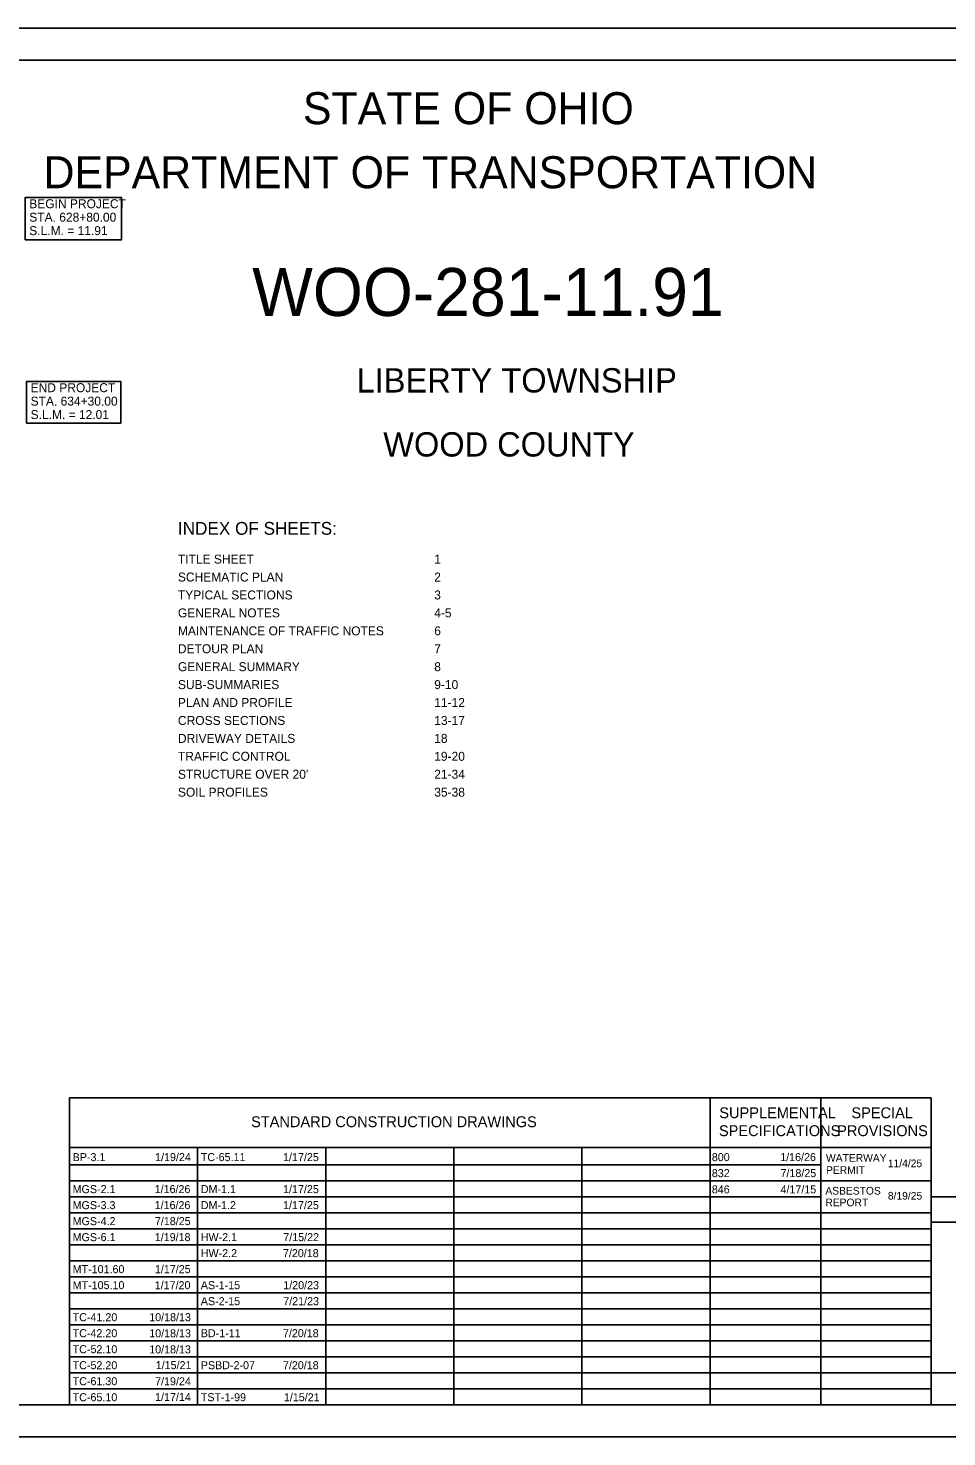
# Model space of a CAD drawing. Extents: x 0 to 39.4, y 0 to 22.
# Drawn here: x 9.51 to 23.84, y 0 to 22 of the extents above; entities that cross this region are included whole.
import ezdxf

# ---------------------------------------------------------------- set-up
doc = ezdxf.new("R2010")
doc.units = 0
for name, color, linetype in [('Default', 7, 'Continuous'), ('SH_Border', 7, 'Continuous'), ('SH_Cut_Line', 7, 'Continuous'), ('SH_Data', 7, 'Continuous'), ('SH_Text', 7, 'Continuous')]:
    doc.layers.add(name, color=color, linetype=linetype)

msp = doc.modelspace()

# ---------------------------------------------------------------- linework, layer by layer
at = {"layer": 'SH_Border'}
msp.add_lwpolyline([(1.5, 21.5), (33.5, 21.5), (33.5, 0.5), (1.5, 0.5)], close=True, dxfattribs=at)
at = {"layer": 'SH_Cut_Line'}
msp.add_lwpolyline([(0, 0), (34, 0), (34, 22), (0, 22)], close=True, dxfattribs=at)
at = {"layer": 'SH_Data'}
for p, q in [((10.15, 5.292), (23.6, 5.292)), ((10.15, 0.5), (10.15, 5.292)), ((20.15, 0.5), (20.15, 5.292)), ((21.875, 0.5), (21.875, 5.292)), ((23.6, 0.5), (23.6, 5.292)), ((10.15, 4.521), (23.6, 4.521)), ((12.15, 0.5), (12.15, 4.521)), ((14.15, 0.5), (14.15, 4.521)), ((16.15, 0.5), (16.15, 4.521)), ((18.15, 0.5), (18.15, 4.521)), ((10.15, 4.25), (21.875, 4.25)), ((10.15, 4), (23.6, 4)), ((10.15, 3.75), (21.875, 3.75)), ((23.6, 0.5), (23.6, 3.75)), ((23.6, 3.75), (26.4, 3.75)), ((10.15, 3.5), (23.6, 3.5)), ((23.6, 3.35), (26.4, 3.35)), ((10.15, 3.25), (23.6, 3.25)), ((10.15, 3), (23.6, 3)), ((10.15, 2.75), (23.6, 2.75)), ((10.15, 2.5), (23.6, 2.5)), ((10.15, 2.25), (23.6, 2.25)), ((10.15, 2), (23.6, 2)), ((10.15, 1.75), (23.6, 1.75)), ((10.15, 1.5), (23.6, 1.5)), ((10.15, 1.25), (23.6, 1.25)), ((10.15, 1), (23.6, 1)), ((10.15, 0.75), (23.6, 0.75)), ((23.6, 0.5), (26.4, 0.5))]:
    msp.add_line(p, q, dxfattribs=at)
for points in [[(9.462, 18.694), (10.961, 18.694), (10.961, 19.356), (9.462, 19.356)], [(9.482, 15.833), (10.952, 15.833), (10.952, 16.483), (9.482, 16.483)], [(23.6, 0.5), (23.6, 1), (26.4, 1), (26.4, 0.5)]]:
    msp.add_lwpolyline(points, close=True, dxfattribs=at)

# ---------------------------------------------------------------- texts
at = {"layer": 'Default'}
for s, height, p in [('BP-3.1', 0.125, (10.201, 4.306)), ('1/19/24', 0.125, (11.488, 4.306)), ('TC-65.11', 0.125, (12.201, 4.306)), ('1/17/25', 0.125, (13.485, 4.306)), ('800', 0.125, (20.176, 4.306)), ('1/16/26', 0.125, (21.243, 4.306)), ('WATERWAY', 0.12, (21.958, 4.296)), ('832', 0.125, (20.176, 4.056)), ('7/18/25', 0.125, (21.248, 4.056)), ('PERMIT', 0.12, (21.958, 4.106)), ('MGS-2.1', 0.125, (10.201, 3.806)), ('1/16/26', 0.125, (11.481, 3.806)), ('DM-1.1', 0.125, (12.201, 3.806)), ('1/17/25', 0.125, (13.485, 3.806)), ('846', 0.125, (20.176, 3.802)), ('4/17/15', 0.125, (21.248, 3.802)), ('MGS-3.3', 0.125, (10.201, 3.556)), ('1/16/26', 0.125, (11.481, 3.556)), ('DM-1.2', 0.125, (12.201, 3.556)), ('1/17/25', 0.125, (13.485, 3.556)), ('MGS-4.2', 0.125, (10.201, 3.306)), ('7/18/25', 0.125, (11.485, 3.306)), ('MGS-6.1', 0.125, (10.201, 3.056)), ('1/19/18', 0.125, (11.483, 3.056)), ('HW-2.1', 0.125, (12.201, 3.056)), ('7/15/22', 0.125, (13.488, 3.056)), ('HW-2.2', 0.125, (12.201, 2.806)), ('7/20/18', 0.125, (13.483, 2.806)), ('MT-101.60', 0.125, (10.201, 2.556)), ('1/17/25', 0.125, (11.485, 2.556)), ('MT-105.10', 0.125, (10.201, 2.306)), ('1/17/20', 0.125, (11.482, 2.306)), ('AS-1-15', 0.125, (12.201, 2.306)), ('1/20/23', 0.125, (13.488, 2.306)), ('AS-2-15', 0.125, (12.201, 2.056)), ('7/21/23', 0.125, (13.488, 2.056)), ('TC-41.20', 0.125, (10.201, 1.806)), ('10/18/13', 0.125, (11.396, 1.806)), ('TC-42.20', 0.125, (10.201, 1.556)), ('10/18/13', 0.125, (11.396, 1.554)), ('BD-1-11', 0.125, (12.201, 1.556)), ('7/20/18', 0.125, (13.483, 1.556)), ('TC-52.10', 0.125, (10.201, 1.306)), ('10/18/13', 0.125, (11.396, 1.303)), ('TC-52.20', 0.125, (10.201, 1.056)), ('1/15/21', 0.125, (11.498, 1.057)), ('PSBD-2-07', 0.125, (12.201, 1.056)), ('7/20/18', 0.125, (13.483, 1.056)), ('TC-61.30', 0.125, (10.201, 0.806)), ('7/19/24', 0.125, (11.488, 0.805)), ('TC-65.10', 0.125, (10.201, 0.556)), ('1/17/14', 0.125, (11.488, 0.559)), ('TST-1-99', 0.125, (12.201, 0.556)), ('1/15/21', 0.125, (13.498, 0.556))]:
    msp.add_text(s, height=height, dxfattribs=at).set_placement(p)
at = {"layer": 'SH_Data'}
for s, p in [('BEGIN PROJECT', (9.524, 19.188)), ('STA. 628+80.00', (9.524, 18.978)), ('S.L.M. = 11.91', (9.524, 18.768)), ('END PROJECT', (9.545, 16.315)), ('STA. 634+30.00', (9.545, 16.105)), ('S.L.M. = 12.01', (9.545, 15.895))]:
    msp.add_text(s, height=0.14, dxfattribs=at).set_placement(p)
at = {"layer": 'SH_Text'}
for s, height, p in [('STATE OF OHIO', 0.5, (13.795, 20.5)), ('DEPARTMENT OF TRANSPORTATION', 0.5, (9.747, 19.5)), ('WOO-281-11.91', 0.75, (13.003, 17.505)), ('LIBERTY TOWNSHIP', 0.38, (14.633, 16.31)), ('WOOD COUNTY', 0.38, (15.048, 15.31)), ('INDEX OF SHEETS:', 0.2, (11.844, 14.088)), ('TITLE SHEET', 0.14, (11.844, 13.638)), ('1', 0.14, (15.844, 13.638)), ('SCHEMATIC PLAN', 0.14, (11.844, 13.358)), ('2', 0.14, (15.844, 13.358)), ('TYPICAL SECTIONS', 0.14, (11.844, 13.078)), ('3', 0.14, (15.844, 13.078)), ('GENERAL NOTES', 0.14, (11.844, 12.798)), ('4-5', 0.14, (15.844, 12.798)), ('MAINTENANCE OF TRAFFIC NOTES', 0.14, (11.844, 12.518)), ('6', 0.14, (15.844, 12.518)), ('DETOUR PLAN', 0.14, (11.844, 12.238)), ('7', 0.14, (15.844, 12.238)), ('GENERAL SUMMARY', 0.14, (11.844, 11.958)), ('8', 0.14, (15.844, 11.958)), ('SUB-SUMMARIES', 0.14, (11.844, 11.678)), ('9-10', 0.14, (15.844, 11.678)), ('PLAN AND PROFILE', 0.14, (11.844, 11.398)), ('11-12', 0.14, (15.844, 11.398)), ('CROSS SECTIONS', 0.14, (11.844, 11.118)), ('13-17', 0.14, (15.844, 11.118)), ('DRIVEWAY DETAILS', 0.14, (11.844, 10.838)), ('18', 0.14, (15.844, 10.838)), ('TRAFFIC CONTROL', 0.14, (11.844, 10.558)), ('19-20', 0.14, (15.844, 10.558)), ("STRUCTURE OVER 20'", 0.14, (11.844, 10.278)), ('21-34', 0.14, (15.844, 10.278)), ('SOIL PROFILES', 0.14, (11.844, 9.998)), ('35-38', 0.14, (15.844, 9.998)), ('SUPPLEMENTAL', 0.17, (20.293, 4.976)), ('SPECIAL', 0.17, (22.354, 4.976)), ('STANDARD CONSTRUCTION DRAWINGS', 0.17, (12.986, 4.836)), ('SPECIFICATIONS', 0.17, (20.287, 4.696)), ('PROVISIONS', 0.17, (22.132, 4.696)), ('11/4/25', 0.12, (22.923, 4.211)), ('ASBESTOS', 0.12, (21.948, 3.783)), ('8/19/25', 0.12, (22.923, 3.705)), ('REPORT', 0.12, (21.948, 3.601))]:
    msp.add_text(s, height=height, dxfattribs=at).set_placement(p)

doc.saveas('drawing.dxf')
